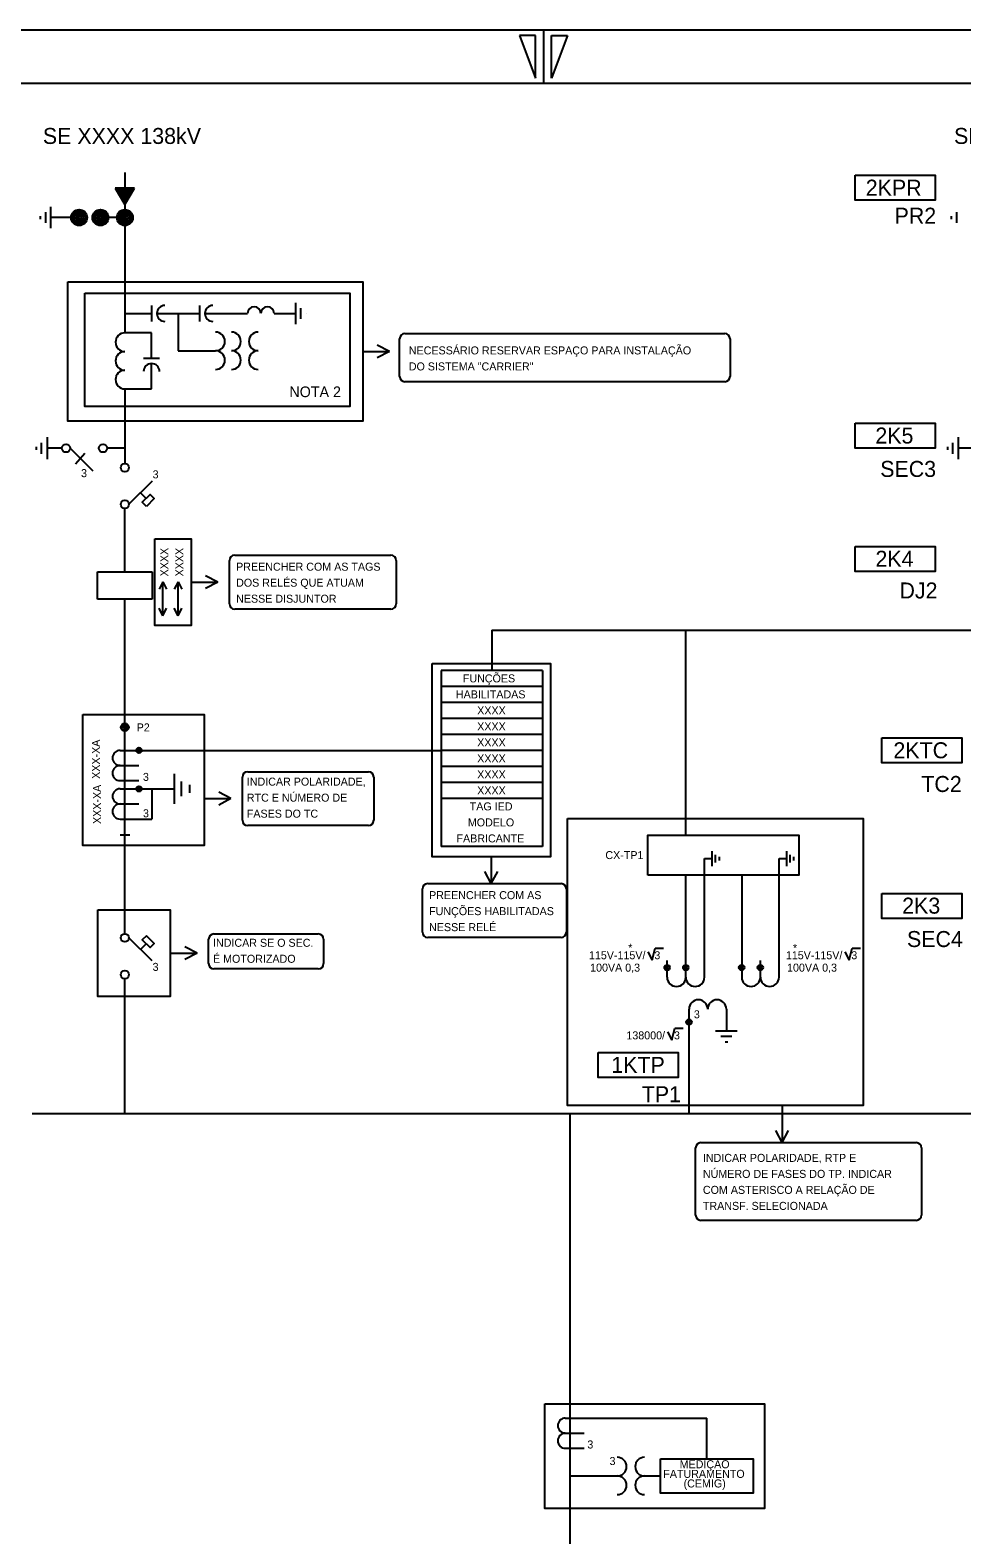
# Model space of a CAD drawing. Extents: x 400 to 1404, y 358 to 952.
# Drawn here: x 807.3 to 982, y 669.8 to 952 of the extents above; entities that cross this region are included whole.
import ezdxf

# ---------------------------------------------------------------- set-up
doc = ezdxf.new("R2010")
doc.units = 0
doc.layers.add('Level 1', color=7, linetype='Continuous')
doc.layers.add('New Level (0)', color=7, linetype='Continuous')

# ---------------------------------------------------------------- blocks, each defined once
blk = doc.blocks.new('_U3')
for p, q in [((-1.47, 0.42), (-0.62, -1.12)), ((-0.62, -1.12), (-0.07, 1.12)), ((-0.07, 1.12), (1.47, 1.12))]:
    blk.add_line(p, q)

msp = doc.modelspace()

# ---------------------------------------------------------------- linework, layer by layer
for p, q in [((825.05, 925.28), (825.05, 895.18)), ((826.86, 922.35), (823.24, 922.35)), ((823.24, 922.35), (825.05, 919.25)), ((826.86, 922.35), (823.24, 922.35)), ((826.68, 922.25), (823.42, 922.25)), ((823.42, 922.25), (825.05, 919.46)), ((826.5, 922.14), (823.6, 922.14)), ((823.6, 922.14), (825.05, 919.67)), ((826.32, 922.04), (823.78, 922.04)), ((823.78, 922.04), (825.05, 919.87)), ((826.14, 921.94), (823.96, 921.94)), ((823.96, 921.94), (825.05, 920.08)), ((825.96, 921.83), (824.15, 921.83)), ((824.15, 921.83), (825.05, 920.29)), ((825.77, 921.73), (824.33, 921.73)), ((824.33, 921.73), (825.05, 920.49)), ((825.59, 921.63), (824.51, 921.63)), ((824.51, 921.63), (825.05, 920.7)), ((825.41, 921.52), (824.69, 921.52)), ((824.69, 921.52), (825.05, 920.9)), ((825.23, 921.42), (824.87, 921.42)), ((824.87, 921.42), (825.05, 921.11)), ((825.05, 919.25), (826.86, 922.35)), ((825.05, 922.35), (825.05, 919.25)), ((825.05, 919.46), (826.68, 922.25)), ((825.05, 919.67), (826.5, 922.14)), ((825.05, 919.87), (826.32, 922.04)), ((825.05, 920.08), (826.14, 921.94)), ((825.05, 920.29), (825.96, 921.83)), ((825.05, 920.49), (825.77, 921.73)), ((825.05, 920.7), (825.59, 921.63)), ((825.05, 920.9), (825.41, 921.52)), ((825.05, 921.11), (825.23, 921.42)), ((809.15, 917.1), (809.15, 916.5)), ((810.15, 917.8), (810.15, 915.8)), ((811.15, 914.8), (811.15, 918.8)), ((980.03, 917.1), (980.03, 916.5)), ((981.03, 917.8), (981.03, 915.8)), ((809.15, 916.8), (809.15, 916.8)), ((812.46, 916.8), (811.15, 916.8)), ((816.46, 916.8), (812.46, 916.8)), ((825.05, 916.8), (820.46, 916.8)), ((980.03, 916.8), (980.03, 916.8)), ((825.05, 884.68), (825.05, 870.68)), ((810.45, 875.61), (810.45, 871.52)), ((981.33, 875.61), (981.33, 871.52)), ((808.41, 873.8), (808.41, 873.27)), ((809.43, 872.54), (809.43, 874.59)), ((813.24, 873.56), (810.45, 873.56)), ((819.12, 869.23), (814.78, 873.56)), ((815.77, 870.62), (817.57, 872.64)), ((825.05, 873.56), (821.72, 873.56)), ((979.3, 873.8), (979.3, 873.27)), ((980.31, 872.54), (980.31, 874.59)), ((984.13, 873.56), (981.33, 873.56)), ((830.16, 867.38), (825.82, 863.05)), ((829.05, 864.15), (827.99, 865.21)), ((825.05, 850.41), (825.05, 862.24)), ((819.93, 845.29), (819.93, 850.41)), ((819.93, 850.41), (830.17, 850.41)), ((830.17, 850.41), (830.17, 845.29)), ((832.17, 848.53), (831.46, 847.11)), ((832.17, 842.16), (832.17, 848.53)), ((832.17, 848.53), (832.87, 847.11)), ((835.02, 848.53), (834.31, 847.11)), ((835.02, 842.16), (835.02, 848.53)), ((835.02, 848.53), (835.72, 847.11)), ((830.17, 845.29), (819.93, 845.29)), ((825.05, 782.54), (825.05, 845.29)), ((832.17, 842.16), (831.46, 843.57)), ((832.17, 842.16), (832.87, 843.57)), ((835.02, 842.16), (834.31, 843.57)), ((835.02, 842.16), (835.72, 843.57)), ((930.24, 801.01), (930.24, 839.44)), ((903.35, 831.91), (884.37, 831.91)), ((884.37, 831.91), (884.37, 798.91)), ((903.35, 831.91), (903.35, 798.91)), ((903.35, 828.91), (884.37, 828.91)), ((903.35, 825.91), (884.37, 825.91)), ((903.35, 822.91), (884.37, 822.91)), ((903.35, 819.91), (884.37, 819.91)), ((824.14, 816.91), (827.68, 816.91)), ((827.68, 816.91), (884.37, 816.91)), ((903.35, 816.91), (884.37, 816.91)), ((824.14, 814.08), (827.68, 814.08)), ((903.35, 813.91), (884.37, 813.91)), ((903.35, 813.91), (884.37, 813.91)), ((824.14, 811.25), (827.68, 811.25)), ((834.29, 812.5), (834.29, 806.91)), ((835.69, 808.31), (835.69, 811.1)), ((837.17, 810.48), (837.17, 808.93)), ((903.35, 810.91), (884.37, 810.91)), ((824.14, 809.7), (827.68, 809.7)), ((825.91, 809.7), (834.29, 809.7)), ((903.35, 807.91), (884.37, 807.91)), ((824.14, 806.87), (827.68, 806.87)), ((824.14, 804.04), (830.1, 804.04)), ((903.35, 798.91), (884.37, 798.91)), ((933.74, 774.4), (933.74, 796.62)), ((933.74, 796.62), (935.14, 796.62)), ((935.14, 798.02), (935.14, 795.22)), ((935.84, 795.92), (935.84, 797.32)), ((936.54, 796.28), (936.54, 796.97)), ((947.73, 774.4), (947.73, 796.62)), ((947.73, 796.62), (949.13, 796.62)), ((949.13, 798.02), (949.13, 795.22)), ((949.83, 795.92), (949.83, 797.32)), ((950.53, 796.28), (950.53, 796.97)), ((930.24, 774.4), (930.24, 793.53)), ((940.73, 793.53), (940.73, 774.4)), ((830.16, 777.43), (825.82, 781.77)), ((829.05, 780.66), (827.99, 779.6)), ((926.74, 774.4), (926.74, 777.5)), ((944.23, 774.4), (944.23, 777.5)), ((825.05, 748.8), (825.05, 774.1)), ((930.85, 748.8), (930.85, 768.4)), ((937.85, 768.4), (937.85, 764.3)), ((935.8, 764.3), (939.9, 764.3)), ((938.87, 763.28), (936.82, 763.28)), ((937.61, 762.26), (938.15, 762.26)), ((1009.5, 748.8), (807.64, 748.8)), ((908.57, 672.04), (908.57, 748.8)), ((907.65, 691.73), (911.19, 691.73)), ((911.19, 691.73), (934.18, 691.73)), ((907.65, 688.9), (911.19, 688.9)), ((907.65, 686.07), (911.19, 686.07)), ((908.57, 680.88), (917.4, 680.88)), ((922.5, 680.88), (925.51, 680.88)), ((908.57, 627.47), (908.57, 672.04))]:
    msp.add_line(p, q)
for points in [[(829.08, 862.65), (828.31, 863.42), (829.79, 864.89), (830.56, 864.12)], [(829.08, 782.17), (828.31, 781.4), (829.79, 779.93), (830.56, 780.69)]]:
    msp.add_lwpolyline(points, close=True)
for centre, radius in [((816.46, 916.8), 1.5), ((816.46, 916.8), 1.25), ((816.46, 916.8), 1), ((816.46, 916.8), 0.75), ((816.46, 916.8), 0.5), ((816.46, 916.8), 0.25), ((820.46, 916.8), 1.5), ((820.46, 916.8), 1.25), ((820.46, 916.8), 1), ((820.46, 916.8), 0.75), ((820.46, 916.8), 0.5), ((820.46, 916.8), 0.25), ((825.05, 916.8), 1.5), ((825.05, 916.8), 1.25), ((825.05, 916.8), 1), ((825.05, 916.8), 0.75), ((825.05, 916.8), 0.5), ((825.05, 916.8), 0.25), ((814.01, 873.56), 0.768), ((820.95, 873.56), 0.768), ((825.05, 869.92), 0.768), ((825.05, 863.05), 0.768), ((825.05, 821.25), 0.729), ((825.05, 821.24), 0.511), ((825.05, 821.24), 0.288), ((827.69, 816.91), 0.511), ((827.69, 816.91), 0.288), ((827.69, 809.7), 0.511), ((827.69, 809.7), 0.288), ((825.05, 781.77), 0.768), ((926.74, 776.19), 0.511), ((926.74, 776.19), 0.288), ((930.24, 776.19), 0.511), ((930.24, 776.19), 0.288), ((940.73, 776.19), 0.511), ((940.73, 776.19), 0.288), ((944.23, 776.19), 0.511), ((944.23, 776.19), 0.288), ((825.05, 774.87), 0.768), ((930.85, 765.96), 0.511), ((930.85, 765.96), 0.288)]:
    msp.add_circle(centre, radius)
for centre, radius, start, end in [((824.14, 815.49), 1.42, 90, 270), ((824.14, 812.66), 1.42, 90, 270), ((824.14, 808.29), 1.42, 90, 270), ((824.14, 805.46), 1.42, 90, 270), ((928.49, 774.4), 1.75, 180, 0), ((931.99, 774.4), 1.75, 180, 0), ((942.48, 774.4), 1.75, 180, 0), ((945.98, 774.4), 1.75, 180, 0), ((932.6, 768.4), 1.75, 0, 180), ((936.1, 768.4), 1.75, 0, 180), ((907.65, 690.31), 1.42, 90, 270), ((907.65, 687.48), 1.42, 90, 270), ((917.4, 682.63), 1.75, 270, 90), ((922.5, 682.63), 1.75, 90, 270), ((917.4, 679.13), 1.75, 270, 90), ((922.5, 679.13), 1.75, 90, 270)]:
    msp.add_arc(centre, radius, start, end)
at = {"layer": 'Level 1'}
for p, q in [((830.05, 900.33), (830.05, 897.33)), ((839.05, 900.33), (839.05, 897.33)), ((857.05, 900.83), (857.05, 896.83)), ((825.05, 898.83), (830.05, 898.83)), ((831.05, 898.83), (839.05, 898.83)), ((835.05, 898.83), (835.05, 891.83)), ((840.05, 898.83), (848.05, 898.83)), ((853.05, 898.83), (857.05, 898.83)), ((858.05, 897.83), (858.05, 899.83)), ((859.05, 898.83), (859.05, 898.83)), ((830.05, 895.18), (825.05, 895.18)), ((830.05, 890.43), (830.05, 895.18)), ((835.05, 891.83), (842.05, 891.83)), ((828.55, 890.43), (831.55, 890.43)), ((830.05, 884.68), (830.05, 889.43)), ((825.05, 884.68), (830.05, 884.68))]:
    msp.add_line(p, q, dxfattribs=at)
for centre, radius, start, end in [((832.55, 898.83), 1.5, 90, 270), ((841.55, 898.83), 1.5, 90, 270), ((849.3, 898.83), 1.25, 0, 180), ((851.8, 898.83), 1.25, 0, 180), ((825.05, 893.43), 1.75, 90, 270), ((842.05, 893.58), 1.75, 270, 90), ((845.05, 893.58), 1.75, 270, 90), ((850.05, 893.58), 1.75, 90, 270), ((825.05, 889.93), 1.75, 90, 270), ((842.05, 890.08), 1.75, 270, 90), ((845.05, 890.08), 1.75, 270, 90), ((850.05, 890.08), 1.75, 90, 270), ((830.05, 887.93), 1.5, 0, 180), ((825.05, 886.43), 1.75, 90, 270)]:
    msp.add_arc(centre, radius, start, end, dxfattribs=at)
at = {"layer": 'New Level (0)'}
for p, q in [((1403.58, 951.96), (562.58, 951.96)), ((1403.58, 951.96), (562.58, 951.96)), ((902.08, 950.96), (899.08, 950.96)), ((899.08, 950.96), (902.08, 942.96)), ((902.08, 942.96), (902.08, 950.96)), ((903.58, 951.96), (903.58, 941.96)), ((905.08, 942.96), (905.08, 950.96)), ((905.08, 950.96), (908.08, 950.96)), ((908.08, 950.96), (905.08, 942.96)), ((1393.58, 941.96), (572.58, 941.96)), ((877.58, 895.06), (907.67, 895.06)), ((907.67, 895.06), (937.54, 895.06)), ((869.65, 891.68), (874.68, 891.68)), ((874.68, 891.68), (872.38, 892.89)), ((874.68, 891.68), (872.38, 890.48)), ((876.58, 887.03), (876.58, 894.06)), ((938.54, 894.06), (938.54, 887.03)), ((937.54, 886.03), (877.58, 886.03)), ((844.64, 844.4), (844.64, 852.51)), ((845.64, 853.51), (853, 853.51)), ((853, 853.51), (874.94, 853.51)), ((875.94, 852.51), (875.94, 844.4)), ((842.49, 848.45), (840.19, 849.66)), ((837.46, 848.45), (842.49, 848.45)), ((842.49, 848.45), (840.19, 847.24)), ((874.94, 843.4), (845.64, 843.4)), ((893.86, 839.44), (1064.74, 839.44)), ((893.86, 839.44), (893.86, 831.91)), ((848.09, 812.92), (855.44, 812.92)), ((855.44, 812.92), (870.71, 812.92)), ((847.09, 803.8), (847.09, 811.92)), ((871.71, 811.92), (871.71, 803.8)), ((830.1, 809.7), (830.1, 804.04)), ((839.9, 807.86), (844.93, 807.86)), ((844.93, 807.86), (842.64, 809.07)), ((844.93, 807.86), (842.64, 806.65)), ((870.71, 802.8), (848.09, 802.8)), ((824.16, 801.09), (825.96, 801.09)), ((893.77, 796.96), (893.77, 791.93)), ((893.77, 791.93), (892.56, 794.23)), ((893.77, 791.93), (894.98, 794.23)), ((880.84, 782.82), (880.84, 790.93)), ((881.84, 791.93), (889.19, 791.93)), ((889.19, 791.93), (906.85, 791.93)), ((907.85, 790.93), (907.85, 782.82)), ((841.75, 782.49), (849.1, 782.49)), ((849.1, 782.49), (861.33, 782.49)), ((906.85, 781.82), (881.84, 781.82)), ((833.56, 778.89), (838.59, 778.89)), ((838.59, 778.89), (836.3, 780.1)), ((838.59, 778.89), (836.3, 777.68)), ((840.75, 776.93), (840.75, 781.49)), ((862.33, 781.49), (862.33, 776.93)), ((861.33, 775.93), (841.75, 775.93)), ((948.32, 750.32), (948.32, 743.37)), ((948.32, 743.37), (947.11, 745.67)), ((948.32, 743.37), (949.53, 745.67)), ((932.08, 729.79), (932.08, 742.37)), ((933.08, 743.37), (973.44, 743.37)), ((974.44, 742.37), (974.44, 729.79)), ((973.44, 728.79), (933.08, 728.79)), ((934.18, 684.11), (934.18, 691.73))]:
    msp.add_line(p, q, dxfattribs=at)
for points in [[(961.98, 924.73), (977, 924.73), (977, 920.04), (961.98, 920.04)], [(814.37, 904.74), (869.65, 904.74), (869.65, 878.63), (814.37, 878.63)], [(817.51, 902.64), (867.26, 902.64), (867.26, 881.36), (817.51, 881.36)], [(961.98, 878.26), (977, 878.26), (977, 873.58), (961.98, 873.58)], [(830.68, 856.56), (837.46, 856.56), (837.46, 840.34), (830.68, 840.34)], [(961.98, 855.16), (977, 855.16), (977, 850.47), (961.98, 850.47)], [(882.68, 833.21), (904.87, 833.21), (904.87, 796.96), (882.68, 796.96)], [(817.18, 823.65), (839.9, 823.65), (839.9, 799.07), (817.18, 799.07)], [(966.99, 819.25), (982.01, 819.25), (982.01, 814.57), (966.99, 814.57)], [(908.08, 804.11), (963.5, 804.11), (963.5, 750.32), (908.08, 750.32)], [(923.14, 793.53), (923.14, 801.01), (951.43, 801.01), (951.43, 793.53)], [(966.99, 790.09), (982.01, 790.09), (982.01, 785.41), (966.99, 785.41)], [(820.01, 787), (833.56, 787), (833.56, 770.78), (820.01, 770.78)], [(913.8, 760.27), (928.81, 760.27), (928.81, 755.59), (913.8, 755.59)], [(903.82, 694.39), (944.99, 694.39), (944.99, 674.78), (903.82, 674.78)], [(925.51, 684.11), (942.85, 684.11), (942.85, 677.64), (925.51, 677.64)]]:
    msp.add_lwpolyline(points, close=True, dxfattribs=at)
for centre, start, end in [((877.58, 894.06), 90, 180), ((937.54, 894.06), 0, 90), ((877.58, 887.03), 180, 270), ((937.54, 887.03), 270, 0), ((845.64, 852.51), 90, 180), ((874.94, 852.51), 0, 90), ((845.64, 844.4), 180, 270), ((874.94, 844.4), 270, 0), ((848.09, 811.92), 90, 180), ((870.71, 811.92), 0, 90), ((848.09, 803.8), 180, 270), ((870.71, 803.8), 270, 0), ((881.84, 790.93), 90, 180), ((906.85, 790.93), 0, 90), ((841.75, 781.49), 90, 180), ((861.33, 781.49), 0, 90), ((881.84, 782.82), 180, 270), ((906.85, 782.82), 270, 0), ((841.75, 776.93), 180, 270), ((861.33, 776.93), 270, 0), ((933.08, 742.37), 90, 180), ((973.44, 742.37), 0, 90), ((933.08, 729.79), 180, 270), ((973.44, 729.79), 270, 0)]:
    msp.add_arc(centre, 1, start, end, dxfattribs=at)

# ---------------------------------------------------------------- block references
for p in [(924.58, 778.72), (961.51, 778.72), (928.25, 763.7)]:
    msp.add_blockref('_U3', p)

# ---------------------------------------------------------------- texts
for s, height, p in [('SE XXXX 138kV', 3, (809.67, 930.61)), ('SE YYYY 138kV', 3, (980.55, 930.61)), ('2KPR', 3, (963.99, 920.91)), ('PR2', 3, (969.39, 915.66)), ('NECESSÁRIO RESERVAR ESPAÇO PARA INSTALAÇÃO ', 1.5, (878.3, 891.15)), ('DO SISTEMA "CARRIER"', 1.5, (878.3, 888.15)), ('NOTA 2', 2, (855.91, 883.14)), ('2K5', 3, (965.79, 874.44)), ('3', 1.5, (816.83, 868.14)), ('3', 1.5, (830.25, 867.91)), ('SEC3', 3, (966.7, 868.18)), ('PREENCHER COM AS TAGS ', 1.5, (845.91, 850.6)), ('2K4', 3, (965.81, 851.34)), ('DOS RELÉS QUE ATUAM ', 1.5, (845.91, 847.6)), ('DJ2', 3, (970.31, 845.39)), ('NESSE DISJUNTOR', 1.5, (845.91, 844.6)), ('FUNÇÕES ', 1.5, (888.43, 829.66)), ('HABILITADAS', 1.5, (887.13, 826.66)), ('XXXX', 1.5, (891.12, 823.66)), ('P2', 1.5, (827.26, 820.47)), ('XXXX', 1.5, (891.12, 820.66)), ('XXXX', 1.5, (891.12, 817.66)), ('2KTC', 3, (969.18, 815.43)), ('XXXX', 1.5, (891.12, 814.66)), ('3', 1.5, (828.44, 811.19)), ('XXXX', 1.5, (891.12, 811.66)), ('INDICAR POLARIDADE, ', 1.5, (847.92, 810.3)), ('XXXX', 1.5, (891.12, 808.66)), ('TC2', 3, (974.41, 809.11)), ('RTC E NÚMERO DE ', 1.5, (847.92, 807.3)), ('TAG IED', 1.5, (889.72, 805.66)), ('3', 1.5, (828.44, 804.37)), ('FASES DO TC', 1.5, (847.92, 804.3)), ('MODELO', 1.5, (889.37, 802.66)), ('FABRICANTE', 1.5, (887.24, 799.66)), ('PREENCHER COM AS ', 1.5, (882.1, 789.02)), ('FUNÇÕES HABILITADAS ', 1.5, (882.1, 786.02)), ('2K3', 3, (970.82, 786.3)), ('NESSE RELÉ', 1.5, (882.1, 783.02)), ('INDICAR SE O SEC. ', 1.5, (841.58, 780.09)), ('SEC4', 3, (971.72, 780.04)), ('É MOTORIZADO', 1.5, (841.58, 777.09)), ('3', 1.5, (830.25, 775.57)), ('1KTP', 3, (916.27, 756.45)), ('TP1', 3, (921.98, 750.95)), ('INDICAR POLARIDADE, RTP E ', 1.5, (933.45, 739.76)), ('NÚMERO DE FASES DO TP. INDICAR ', 1.5, (933.45, 736.76)), ('COM ASTERISCO A RELAÇÃO DE ', 1.5, (933.45, 733.76)), ('TRANSF. SELECIONADA', 1.5, (933.45, 730.76)), ('3', 1.5, (911.78, 686.03)), ('3', 1.5, (915.94, 682.92)), ('MEDIÇÃO', 1.5, (929.09, 682.32)), ('FATURAMENTO', 1.5, (926.02, 680.52)), ('(CEMIG)', 1.5, (929.83, 678.72))]:
    msp.add_text(s, height=height).set_placement(p)
for s, rotation, p in [('XXXX', 90, (833.17, 849.53)), ('XXXX', 90, (836.02, 849.53)), ('XXX-XA', 90, (820.37, 811.57)), ('XXX-XA', 90, (820.58, 803.11)), ('CX-TP1', 360, (915.16, 796.53)), ('115V-115V/   3', 360, (912.08, 777.75)), ('*', 360, (919.44, 779.17)), ('115V-115V/   3', 360, (949.01, 777.75)), ('*', 360, (950.34, 779.11)), ('100VA 0,3', 360, (912.3, 775.43)), ('100VA 0,3', 360, (949.23, 775.43)), ('3', 360, (931.76, 766.68)), ('138000/   3', 360, (919.1, 762.73))]:
    msp.add_text(s, height=1.5, rotation=rotation).set_placement(p)

doc.saveas('drawing.dxf')
